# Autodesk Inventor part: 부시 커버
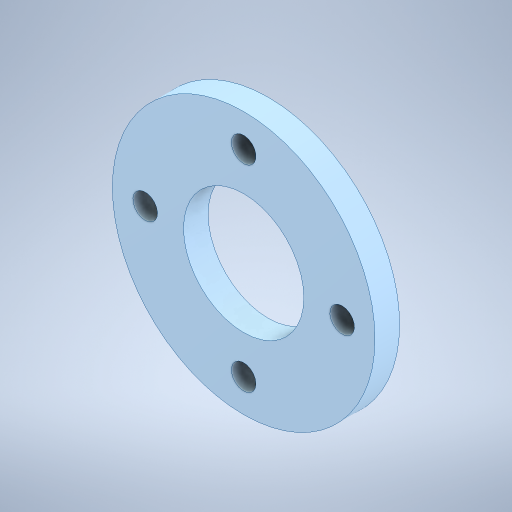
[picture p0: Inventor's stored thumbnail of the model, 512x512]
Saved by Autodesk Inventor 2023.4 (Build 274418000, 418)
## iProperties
Created: 2024-05
Part Number: 부시 커버
Material: 강철, 연강
Document SubType Name: Modeling
Designer: EDU-001
Density: 7.85 g/cm^3
Appearance: 기본값
Author: jhkim
Sending System: Autodesk Inventor 2025
Preprocessor: ST-DEVELOPER v20
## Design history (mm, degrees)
node "부시 커버1"
node "솔리드2"
node "솔리드1"
